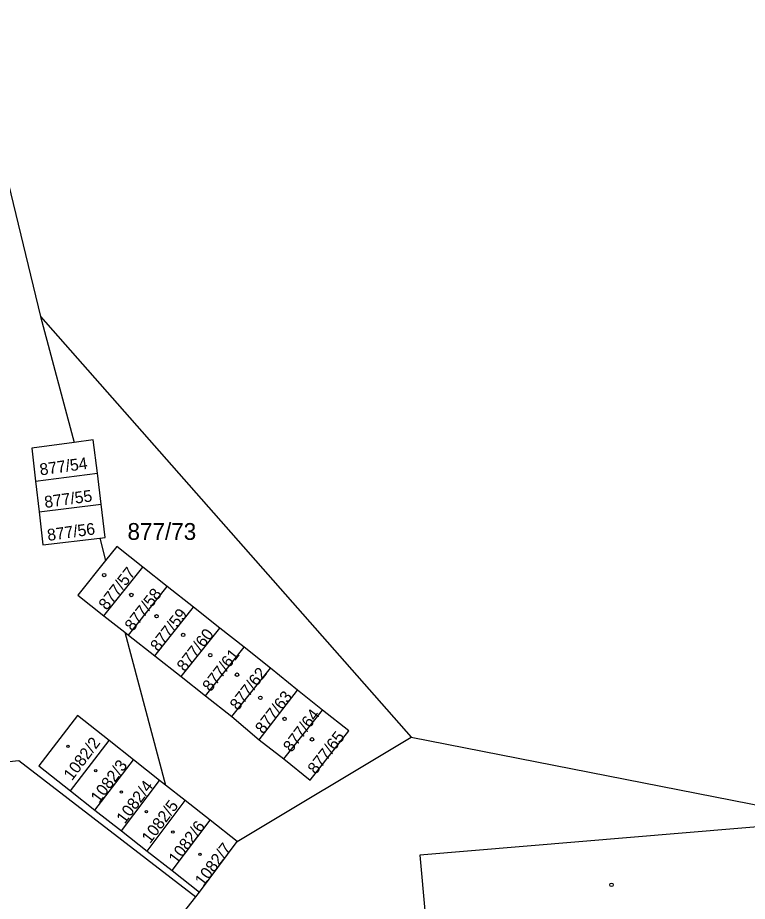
# Model space of a CAD drawing. Extents: x -869103 to -863415, y -1015889 to -1012477.
# Drawn here: x -866422.9 to -866349.1, y -1013922.4 to -1013833 of the extents above; entities that cross this region are included whole.
import ezdxf

# ---------------------------------------------------------------- set-up
doc = ezdxf.new("R2010")
doc.units = 0
for name, color, linetype in [('Hranice parcel', 7, 'Continuous'), ('Parcelní čísla', 7, 'Continuous'), ('Značky budov', 7, 'Continuous')]:
    doc.layers.add(name, color=color, linetype=linetype)

msp = doc.modelspace()

# ---------------------------------------------------------------- linework, layer by layer
at = {"layer": 'Hranice parcel'}
for p, q in [((-866420.57, -1013863.24), (-866383.06, -1013905.77)), ((-866420.57, -1013863.24), (-866417.16, -1013875.99)), ((-866421.07, -1013879.89), (-866414.82, -1013879.1)), ((-866414.43, -1013882.23), (-866414.82, -1013879.1)), ((-866421.07, -1013879.89), (-866420.71, -1013883)), ((-866420.71, -1013883), (-866414.43, -1013882.23)), ((-866414.58, -1013885.66), (-866413.98, -1013887.9)), ((-866414.16, -1013893.5), (-866410.21, -1013888.6)), ((-866407.75, -1013890.54), (-866410.21, -1013888.6)), ((-866411.68, -1013895.45), (-866407.75, -1013890.54)), ((-866405.08, -1013892.64), (-866407.75, -1013890.54)), ((-866409.01, -1013897.55), (-866405.08, -1013892.64)), ((-866402.42, -1013894.74), (-866405.08, -1013892.64)), ((-866414.16, -1013893.5), (-866412.04, -1013895.17)), ((-866412.04, -1013895.17), (-866411.68, -1013895.45)), ((-866412.04, -1013895.17), (-866407.91, -1013910.62)), ((-866406.34, -1013899.65), (-866402.42, -1013894.74)), ((-866399.95, -1013896.69), (-866402.42, -1013894.74)), ((-866411.68, -1013895.45), (-866409.01, -1013897.55)), ((-866403.87, -1013901.6), (-866399.95, -1013896.69)), ((-866397.29, -1013898.79), (-866399.95, -1013896.69)), ((-866409.01, -1013897.55), (-866406.34, -1013899.65)), ((-866401.2, -1013903.7), (-866397.29, -1013898.79)), ((-866394.56, -1013901.04), (-866397.29, -1013898.79)), ((-866406.34, -1013899.65), (-866403.87, -1013901.6)), ((-866403.87, -1013901.6), (-866401.2, -1013903.7)), ((-866398.44, -1013906.03), (-866394.56, -1013901.04)), ((-866392.05, -1013903.03), (-866394.56, -1013901.04)), ((-866395.96, -1013907.95), (-866392.05, -1013903.03)), ((-866401.2, -1013903.7), (-866398.44, -1013906.03)), ((-866417.54, -1013911.19), (-866413.64, -1013906.11)), ((-866411.17, -1013908.05), (-866413.64, -1013906.11)), ((-866400.67, -1013916.32), (-866383.06, -1013905.77)), ((-866398.44, -1013906.03), (-866395.96, -1013907.95)), ((-866383.06, -1013905.77), (-866333.23, -1013915.55)), ((-866415.06, -1013913.14), (-866411.17, -1013908.05)), ((-866408.52, -1013910.14), (-866411.17, -1013908.05)), ((-866412.39, -1013915.23), (-866408.52, -1013910.14)), ((-866407.91, -1013910.62), (-866408.52, -1013910.14)), ((-866417.54, -1013911.19), (-866415.06, -1013913.14)), ((-866405.92, -1013912.19), (-866407.91, -1013910.62)), ((-866409.77, -1013917.29), (-866405.92, -1013912.19)), ((-866403.42, -1013914.15), (-866405.92, -1013912.19)), ((-866415.06, -1013913.14), (-866412.39, -1013915.23)), ((-866407.26, -1013919.26), (-866403.42, -1013914.15)), ((-866400.67, -1013916.32), (-866403.42, -1013914.15)), ((-866412.39, -1013915.23), (-866409.77, -1013917.29)), ((-866404.49, -1013921.43), (-866400.67, -1013916.32)), ((-866409.77, -1013917.29), (-866407.26, -1013919.26)), ((-866407.26, -1013919.26), (-866404.49, -1013921.43)), ((-866404.85, -1013921.93), (-866404.49, -1013921.43))]:
    msp.add_line(p, q, dxfattribs=at)
for points in [[(-866433.93, -1013833.04), (-866425.87, -1013841.53), (-866420.57, -1013863.24)], [(-866414.82, -1013879.1), (-866415.23, -1013875.73), (-866417.16, -1013875.99)], [(-866417.16, -1013875.99), (-866421.46, -1013876.56), (-866421.07, -1013879.89)], [(-866414.58, -1013885.66), (-866414.02, -1013885.6), (-866414.43, -1013882.23)], [(-866420.71, -1013883), (-866420.32, -1013886.33), (-866414.58, -1013885.66)], [(-866410.21, -1013888.6), (-866412.86, -1013886.51), (-866413.98, -1013887.9)], [(-866413.98, -1013887.9), (-866416.81, -1013891.41), (-866414.16, -1013893.5)], [(-866395.96, -1013907.95), (-866393.28, -1013910.11), (-866389.37, -1013905.15), (-866392.05, -1013903.03)], [(-866413.64, -1013906.11), (-866416.82, -1013903.6), (-866420.74, -1013908.68), (-866417.54, -1013911.19)], [(-866486.37, -1013914.62), (-866482.98, -1013914.41), (-866422.75, -1013908.14), (-866404.85, -1013921.93)], [(-866344.8, -1013914.58), (-866382.18, -1013917.72), (-866381.09, -1013930.01), (-866343.75, -1013926.83), (-866344.8, -1013914.58)], [(-866412.25, -1013933.1), (-866412.49, -1013931.58), (-866404.85, -1013921.93)]]:
    msp.add_lwpolyline(points, dxfattribs=at)
at = {"layer": 'Značky budov'}
for centre, radius in [((-866414.127, -1013889.389), 0.175), ((-866411.387, -1013891.399), 0.175), ((-866408.827, -1013893.549), 0.175), ((-866406.137, -1013895.439), 0.175), ((-866403.397, -1013897.489), 0.175), ((-866400.697, -1013899.459), 0.175), ((-866398.327, -1013901.799), 0.175), ((-866395.877, -1013903.929), 0.175), ((-866393.107, -1013905.999), 0.175), ((-866417.795, -1013906.699), 0.123), ((-866414.985, -1013909.159), 0.123), ((-866412.385, -1013911.329), 0.123), ((-866409.855, -1013913.309), 0.123), ((-866407.185, -1013915.369), 0.123), ((-866404.445, -1013917.609), 0.123), ((-866362.807, -1013920.699), 0.175)]:
    msp.add_circle(centre, radius, dxfattribs=at)

# ---------------------------------------------------------------- texts
at = {"layer": 'Parcelní čísla'}
for s, rotation, p in [('877/54', 8, (-866420.577, -1013879.319)), ('877/55', 8, (-866420.097, -1013882.609)), ('877/56', 8, (-866419.807, -1013885.939)), ('877/57', 52, (-866413.871, -1013893.016)), ('877/58', 52, (-866411.231, -1013895.146)), ('877/59', 52, (-866408.641, -1013897.196)), ('877/60', 52, (-866405.961, -1013899.226)), ('877/61', 52, (-866403.371, -1013901.266)), ('877/62', 52, (-866400.591, -1013903.146)), ('877/63', 52, (-866398.031, -1013905.526)), ('877/64', 53, (-866395.187, -1013907.386)), ('877/65', 52, (-866392.721, -1013909.606)), ('1082/2', 53, (-866417.384, -1013910.238)), ('1082/3', 53, (-866414.644, -1013912.518)), ('1082/4', 53, (-866412.044, -1013914.608)), ('1082/5', 53, (-866409.484, -1013916.598)), ('1082/6', 53, (-866406.774, -1013918.688)), ('1082/7', 53, (-866404.104, -1013920.928))]:
    msp.add_text(s, height=1.19, rotation=rotation, dxfattribs=at).set_placement(p)
msp.add_text('877/73', height=1.7, dxfattribs=at).set_placement((-866411.77, -1013885.83))

doc.saveas('drawing.dxf')
